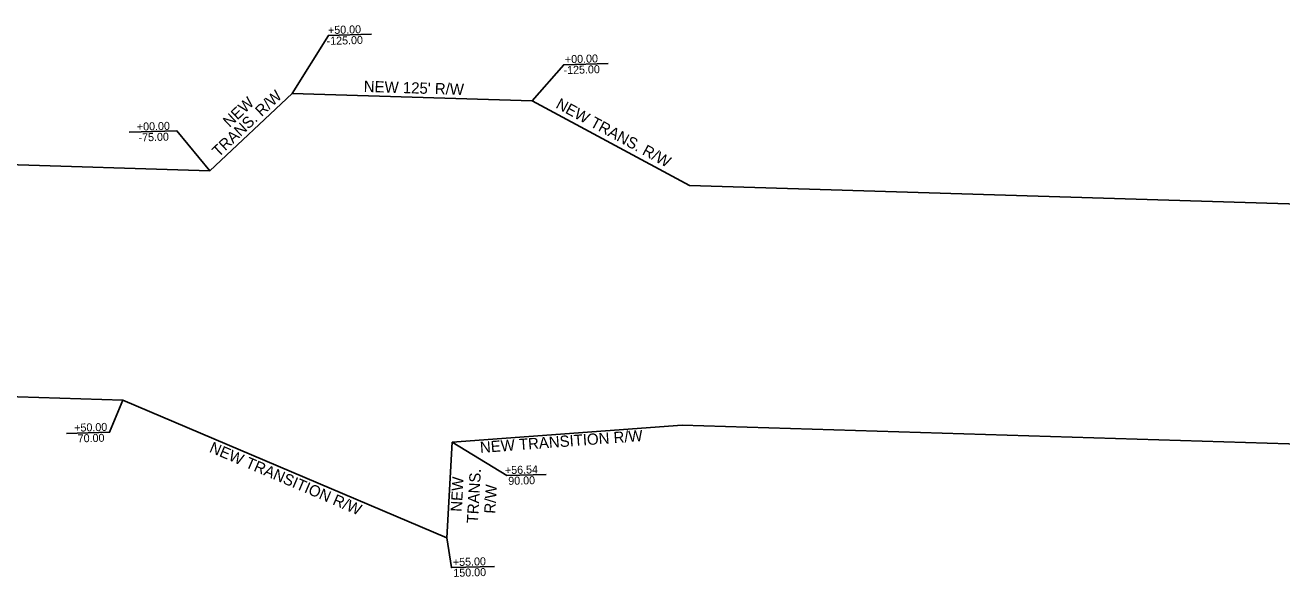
# Model space of a CAD drawing. Extents: x 2003184 to 2010449, y 855784 to 861212.
# Drawn here: x 2006844 to 2007629, y 857959 to 858305 of the extents above; entities that cross this region are included whole.
import ezdxf

# ---------------------------------------------------------------- set-up
doc = ezdxf.new("R2010")
doc.units = 0
doc.layers.add('RD_PD_RW', color=7, linetype='Continuous')
doc.layers.add('RD_PD_RW_TX', color=7, linetype='Continuous')

msp = doc.modelspace()

# ---------------------------------------------------------------- linework, layer by layer
at = {"layer": 'RD_PD_RW'}
for p, q in [((2006959.36, 858213.36), (2007010.87, 858261.8)), ((2007010.87, 858261.8), (2007160.8, 858257.2)), ((2007259.22, 858204.16), (2007160.8, 858257.2)), ((2006559.55, 858225.63), (2006959.36, 858213.36)), ((2007259.22, 858204.16), (2008058.84, 858179.62)), ((2006580.09, 858079.93), (2006904.94, 858069.96)), ((2006904.94, 858069.96), (2007107.39, 857983.71)), ((2007110.77, 858043.64), (2007254.62, 858054.23)), ((2007254.62, 858054.23), (2008154.19, 858026.62)), ((2007107.39, 857983.71), (2007110.77, 858043.64))]:
    msp.add_line(p, q, dxfattribs=at)
at = {"layer": 'RD_PD_RW_TX'}
for points in [[(2007060.3, 858298.77), (2007033.51, 858298.01), (2007010.87, 858261.8)], [(2007208.36, 858280.5), (2007180.56, 858279.72), (2007160.8, 858257.2)], [(2006908.87, 858237.44), (2006938.82, 858238.28), (2006959.36, 858213.36)], [(2006869.71, 858049.12), (2006896.72, 858049.88), (2006904.94, 858069.96)], [(2007169.6, 858023.45), (2007145.04, 858022.76), (2007110.77, 858043.64)], [(2007137.31, 857965.95), (2007110.37, 857965.19), (2007107.39, 857983.71)]]:
    msp.add_lwpolyline(points, dxfattribs=at)

# ---------------------------------------------------------------- texts
for s, height, rotation, p in [('+50.00', 5, 1.60931, (2007033.29, 858298.88)), ('-125.00', 5, 1.60931, (2007032.44, 858292.11)), ('+00.00', 5, 1.60931, (2007181.35, 858280.62)), ('-125.00', 5, 1.60931, (2007180.5, 858273.84)), ("NEW 125' R/W", 7, 358.24216, (2007055.46, 858262.73)), ('TRANS. R/W', 7, 43.24221, (2006964.81, 858221.62)), ('NEW', 7, 43.24221, (2006971.62, 858240.2)), ('NEW TRANS. R/W', 7, 331.67711, (2007175.03, 858253.01)), ('+00.00', 5, 1.60931, (2006913.84, 858238.46)), ('-75.00', 5, 1.60931, (2006914.88, 858231.73)), ('+50.00', 5, 1.60931, (2006874.68, 858050.14)), ('70.00', 5, 1.60931, (2006876.85, 858043.45)), ('NEW TRANSITION R/W', 7, 4.21131, (2007128.42, 858036.86)), ('NEW TRANSITION R/W', 7, 336.92421, (2006958.55, 858037.7)), ('NEW', 7, 86.77041, (2007116.78, 857999.94)), ('TRANS.', 7, 86.77041, (2007126.89, 857992.69)), ('+56.54', 5, 1.60931, (2007143.86, 858023.6)), ('90.00', 5, 1.60931, (2007145.94, 858016.91)), ('R/W', 7, 86.77041, (2007137.75, 857998.76)), ('+55.00', 5, 1.60931, (2007111.34, 857966.1)), ('150.00', 5, 1.60931, (2007111.62, 857959.35))]:
    msp.add_text(s, height=height, rotation=rotation, dxfattribs=at).set_placement(p)

doc.saveas('drawing.dxf')
